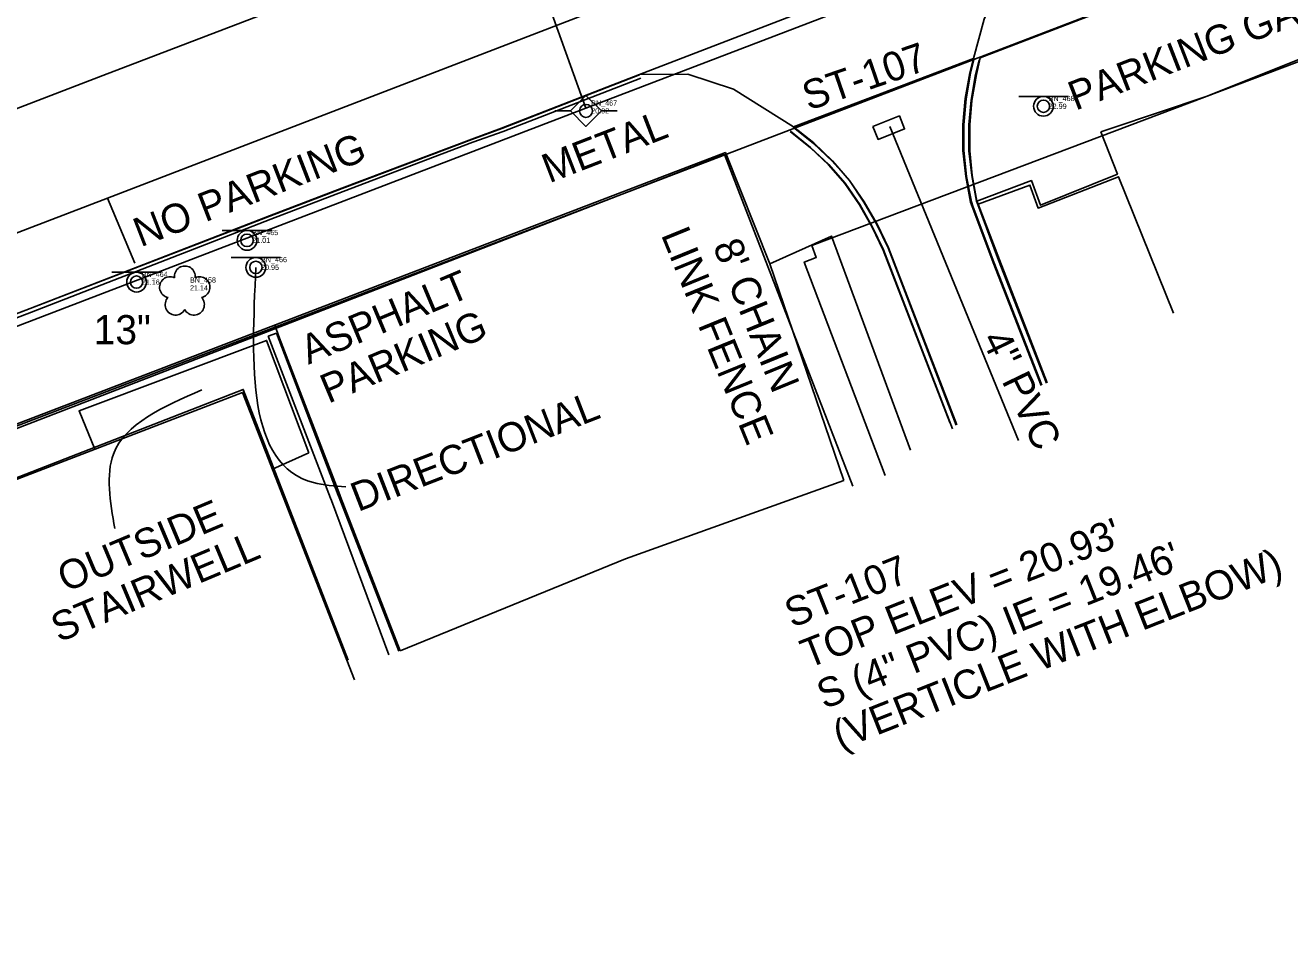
# Model space of a CAD drawing. Extents: x 509744 to 512285, y 1314862 to 1316822.
# Drawn here: x 509949 to 510070.6, y 1315115.3 to 1315204 of the extents above; entities that cross this region are included whole.
import ezdxf

# ---------------------------------------------------------------- set-up
doc = ezdxf.new("R2010")
doc.units = 0
for name, color, linetype in [('Building_ep', 7, 'Continuous'), ('CatchBasin_ep', 7, 'Continuous'), ('CGBack_ep', 7, 'Continuous'), ('CGFace_ep', 7, 'Continuous'), ('ConcSlabs_ep', 7, 'Continuous'), ('Driveway_ep', 7, 'Continuous'), ('ElecAer_ep', 7, 'Continuous'), ('Fence_ep', 7, 'Continuous'), ('LaneLine_ep', 7, 'Continuous'), ('NonPlottingEle_dp', 7, 'Continuous'), ('PavtAsphalt_ep', 7, 'Continuous'), ('PavtBreak_ep', 7, 'Continuous'), ('PavtMisc_ep', 7, 'Continuous'), ('PipeCulvert_ep', 7, 'Continuous'), ('PMRK_ep', 7, 'Continuous'), ('PoleShared_ep', 7, 'Continuous'), ('RWLine_ep', 7, 'Continuous'), ('SidewalkBack_ep', 7, 'Continuous'), ('SignSingle_ep', 7, 'Continuous'), ('Slopes_ep', 7, 'Continuous'), ('TextElevLabel', 7, 'Continuous'), ('TextPtLabel', 7, 'Continuous'), ('TextTopoLabel_ep', 7, 'Continuous'), ('TextUtilLabel_ep', 7, 'Continuous'), ('Tree_ep', 7, 'Continuous')]:
    doc.layers.add(name, color=color, linetype=linetype)

msp = doc.modelspace()

# ---------------------------------------------------------------- linework, layer by layer
at = {"layer": 'Building_ep'}
msp.add_line((509976.25, 1315162.89), (509972.77, 1315161.34), dxfattribs=at)
for points in [[(510031.67, 1315160.73), (510023.9, 1315181.24), (510025.05, 1315181.67), (510024.61, 1315182.82), (510259.1, 1315271.46), (510282.99, 1315280.49), (510283.72, 1315280.77), (510283.22, 1315282.11), (510309.92, 1315292.28), (510311.75, 1315292.98), (510312.2, 1315291.8), (510313.38, 1315292.25), (510318.66, 1315278.4)], [(509955.69, 1315163.24), (509954.18, 1315166.93), (509972.2, 1315173.7), (509976.25, 1315162.89)], [(509838.61, 1315118.22), (509969.9, 1315168.71), (509980.66, 1315141.08)]]:
    msp.add_lwpolyline(points, dxfattribs=at)
at = {"layer": 'CatchBasin_ep'}
msp.add_lwpolyline([(510030.5, 1315194.29), (510033.04, 1315195.29), (510033.54, 1315194.04), (510031, 1315193.04)], close=True, dxfattribs=at)
at = {"layer": 'CGBack_ep'}
for points in [[(510040.72, 1315200.67), (510040.37, 1315199.29), (510039.93, 1315196.81), (510039.73, 1315194.44), (510039.73, 1315191.94), (510040, 1315189.55), (510040.46, 1315187.1), (510040.57, 1315186.79), (510042.57, 1315181.42), (510047.18, 1315169.59)], [(509813.71, 1315124.27), (509825.79, 1315128.91), (509831.2, 1315131.02), (509839.43, 1315134.21), (509846.9, 1315137.07), (509851.56, 1315138.88), (509884.3, 1315151.27), (509916.92, 1315163.93), (509949.61, 1315176.43), (509972.61, 1315185.37), (509979.57, 1315188.02), (509992.04, 1315192.76), (509994.94, 1315193.78), (510005.05, 1315197.7), (510008.18, 1315198.91)], [(510022.56, 1315193.82), (510024.51, 1315192.27), (510026.26, 1315190.62), (510027.83, 1315188.82), (510029.23, 1315186.77), (510030.46, 1315184.6), (510031.52, 1315182.42), (510038.15, 1315165.22)], [(509972.35, 1315174.12), (509978.36, 1315158.53), (509978.43, 1315158.31), (509983.97, 1315143.48)]]:
    msp.add_lwpolyline(points, dxfattribs=at)
at = {"layer": 'CGFace_ep'}
msp.add_line((509972.35, 1315174.12), (509973.15, 1315174.4), dxfattribs=at)
for points in [[(510040.22, 1315200.8), (510039.89, 1315199.41), (510039.45, 1315196.95), (510039.23, 1315194.45), (510039.23, 1315191.96), (510039.5, 1315189.48), (510039.97, 1315187.02), (510040.11, 1315186.6), (510042.13, 1315181.23), (510046.74, 1315169.4)], [(509813.59, 1315124.59), (509825.66, 1315129.25), (509831.06, 1315131.39), (509839.29, 1315134.56), (509846.77, 1315137.4), (509851.43, 1315139.21), (509884.16, 1315151.63), (509916.8, 1315164.26), (509949.48, 1315176.78), (509972.5, 1315185.65), (509979.46, 1315188.3), (509991.93, 1315193.04), (509994.82, 1315194.09), (510004.92, 1315198.02), (510008.05, 1315199.23)], [(510022.82, 1315194.2), (510024.78, 1315192.65), (510026.59, 1315190.94), (510028.23, 1315189.07), (510029.63, 1315187.01), (510030.86, 1315184.85), (510031.95, 1315182.6), (510038.49, 1315165.56)], [(509984.92, 1315143.81), (509979.19, 1315158.6), (509979.09, 1315158.81), (509973.15, 1315174.4)]]:
    msp.add_lwpolyline(points, dxfattribs=at)
at = {"layer": 'ConcSlabs_ep'}
msp.add_lwpolyline([(510040.63, 1315186.81), (510045.59, 1315188.64), (510046.37, 1315186.43), (510054.11, 1315189.45), (510059.39, 1315176.32)], dxfattribs=at)
at = {"layer": 'Driveway_ep'}
msp.add_line((510020.58, 1315181.06), (510027.7, 1315160.24), dxfattribs=at)
for points in [[(510045.95, 1315213.87), (510042.88, 1315208.24), (510041.2, 1315204.61), (510040.15, 1315200.82), (510039.82, 1315199.43), (510039.38, 1315196.98), (510039.15, 1315194.45), (510039.15, 1315191.96), (510039.43, 1315189.47), (510039.89, 1315187.01), (510040.04, 1315186.57), (510042.06, 1315181.2), (510046.67, 1315169.38)], [(510008.04, 1315199.27), (510012.69, 1315199.32), (510017.1, 1315197.85), (510022.85, 1315194.24), (510024.8, 1315192.69), (510026.62, 1315190.97), (510028.26, 1315189.09), (510029.66, 1315187.03), (510030.89, 1315184.87), (510031.99, 1315182.61), (510038.56, 1315165.59)], [(509972.98, 1315175.18), (509973.44, 1315173.91), (509979.23, 1315158.87), (509979.31, 1315158.65), (509985.03, 1315143.85)]]:
    msp.add_lwpolyline(points, dxfattribs=at)
at = {"layer": 'ElecAer_ep'}
msp.add_line((510002.91, 1315196.03), (509981.67, 1315254.87), dxfattribs=at)
msp.add_lwpolyline([(510322.54, 1315318.27), (510002.91, 1315196.03), (509851.1, 1315137.82), (509841.44, 1315118.67)], dxfattribs=at)
at = {"layer": 'Fence_ep'}
msp.add_lwpolyline([(510028.58, 1315159.69), (510016.24, 1315191.57), (509972.9, 1315174.8), (509819.68, 1315115.6)], dxfattribs=at)
at = {"layer": 'LaneLine_ep'}
msp.add_lwpolyline([(510329.98, 1315342.27), (510306.63, 1315333.33), (510283.28, 1315324.38), (510259.94, 1315315.44), (510236.59, 1315306.49), (510213.25, 1315297.55), (510189.9, 1315288.61), (510166.56, 1315279.66), (510143.21, 1315270.72), (510119.87, 1315261.77), (510096.52, 1315252.83), (510073.18, 1315243.89), (510049.83, 1315234.94), (510026.49, 1315226), (510003.14, 1315217.05), (509979.8, 1315208.11), (509956.45, 1315199.17), (509933.11, 1315190.22), (509909.76, 1315181.28), (509886.41, 1315172.33), (509863.07, 1315163.39), (509839.72, 1315154.44), (509808.5, 1315142.48)], dxfattribs=at)
at = {"layer": 'PavtAsphalt_ep'}
msp.add_lwpolyline([(509813.54, 1315124.7), (509825.63, 1315129.33), (509831.05, 1315131.4), (509839.29, 1315134.57), (509846.77, 1315137.41), (509851.43, 1315139.22), (509884.12, 1315151.73), (509916.79, 1315164.27), (509949.48, 1315176.78), (509972.49, 1315185.69), (509979.45, 1315188.33), (509991.92, 1315193.07), (509994.8, 1315194.13), (510004.91, 1315198.06), (510008.04, 1315199.27), (510040.7, 1315211.86), (510048.47, 1315214.83), (510051.93, 1315216.06), (510084.65, 1315228.47), (510117.34, 1315240.98), (510150.02, 1315253.51), (510182.71, 1315266), (510215.38, 1315278.54), (510256.49, 1315294.51)], dxfattribs=at)
at = {"layer": 'PavtBreak_ep'}
msp.add_line((510022.85, 1315194.24), (510040.15, 1315200.82), dxfattribs=at)
msp.add_lwpolyline([(509956.9, 1315187.39), (509980.24, 1315196.35), (510003.58, 1315205.32), (510026.92, 1315214.28), (510050.25, 1315223.25), (510054.84, 1315225.01)], dxfattribs=at)
at = {"layer": 'PavtMisc_ep'}
for points in [[(510244.98, 1315267.81), (510208.36, 1315253.88), (510148.37, 1315230.91), (510099.37, 1315211.92), (510062.55, 1315197.17), (510053.37, 1315194.09)], [(510040.5, 1315187.1), (510045.74, 1315189.07), (510046.62, 1315186.71), (510054.01, 1315189.7), (510052.42, 1315193.76)], [(510052.42, 1315193.76), (510053.37, 1315194.09)], [(509985.03, 1315143.85), (510006.71, 1315152.71), (510027.7, 1315160.24)]]:
    msp.add_lwpolyline(points, dxfattribs=at)
at = {"layer": 'PipeCulvert_ep'}
msp.add_line((510032.12, 1315194.29), (510044.49, 1315164.07), dxfattribs=at)
at = {"layer": 'PMRK_ep'}
for points in [[(509956.9, 1315187.39), (509889.16, 1315161.41)], [(509959.55, 1315181.13), (509956.9, 1315187.39)]]:
    msp.add_lwpolyline(points, dxfattribs=at)
at = {"layer": 'PoleShared_ep'}
for p, q in [((509999.92, 1315195.78), (510001.42, 1315195.78)), ((510005.9, 1315195.78), (510004.4, 1315195.78))]:
    msp.add_line(p, q, dxfattribs=at)
msp.add_lwpolyline([(510001.42, 1315195.78), (510002.91, 1315197.27), (510004.4, 1315195.78), (510002.91, 1315194.29), (510001.42, 1315195.78)], dxfattribs=at)
msp.add_circle((510002.91, 1315195.78), 0.625, dxfattribs=at)
at = {"layer": 'RWLine_ep'}
msp.add_line((509817.13, 1315115.31), (510540.74, 1315392.41), dxfattribs=at)
at = {"layer": 'SidewalkBack_ep'}
for points in [[(510047.26, 1315169.62), (510042.65, 1315181.45), (510040.63, 1315186.81), (510040.5, 1315187.1), (510040.03, 1315189.56), (510039.81, 1315191.94), (510039.81, 1315194.44), (510040.01, 1315196.79), (510040.45, 1315199.27), (510040.81, 1315200.88), (510064.15, 1315209.84), (510087.49, 1315218.79), (510110.83, 1315227.75), (510134.17, 1315236.71), (510157.51, 1315245.66), (510180.85, 1315254.62), (510204.2, 1315263.57), (510227.54, 1315272.53), (510250.88, 1315281.48), (510274.22, 1315290.44), (510277.93, 1315291.86)], [(510022.54, 1315193.8), (510024.48, 1315192.23), (510026.22, 1315190.59), (510027.78, 1315188.8), (510029.19, 1315186.74), (510030.42, 1315184.58), (510031.47, 1315182.4), (510037.89, 1315165.82)], [(509817.13, 1315115.51), (509829.53, 1315120.26), (509852.88, 1315129.2), (509876.23, 1315138.14), (509899.57, 1315147.08), (509922.92, 1315156.02), (509946.27, 1315164.96), (509969.62, 1315173.89), (509992.96, 1315182.83), (510016.31, 1315191.77), (510020.58, 1315181.06), (510026.51, 1315183.74), (510034.11, 1315163.14)]]:
    msp.add_lwpolyline(points, dxfattribs=at)
at = {"layer": 'SignSingle_ep'}
for p, q in [((510044.51, 1315197.17), (510049.26, 1315197.17)), ((509967.94, 1315184.28), (509972.69, 1315184.28)), ((509968.8, 1315181.68), (509973.55, 1315181.68)), ((509957.32, 1315180.26), (509962.07, 1315180.26))]:
    msp.add_line(p, q, dxfattribs=at)
for centre, radius in [((510046.89, 1315196.22), 0.95), ((510046.89, 1315196.22), 0.594), ((509970.32, 1315183.33), 0.95), ((509970.32, 1315183.33), 0.594), ((509971.17, 1315180.73), 0.95), ((509971.17, 1315180.73), 0.594), ((509959.7, 1315179.31), 0.95), ((509959.7, 1315179.31), 0.594)]:
    msp.add_circle(centre, radius, dxfattribs=at)
at = {"layer": 'Slopes_ep'}
msp.add_lwpolyline([(509980.03, 1315142.95), (509969.95, 1315168.99), (509924.51, 1315151.28), (509884.5, 1315135.91), (509856.15, 1315125.1), (509838.49, 1315118.26)], dxfattribs=at)
at = {"layer": 'TextTopoLabel_ep'}
for points in [[(509979.82, 1315159.62), (509976.71, 1315160.03), (509971.17, 1315180.73)], [(509965.96, 1315168.95), (509957.48, 1315162.78), (509957.61, 1315155.63)]]:
    msp.add_spline(points, degree=3, dxfattribs=at)
at = {"layer": 'Tree_ep'}
for centre, start, end in [((509964.34, 1315179.86), 352.1546, 187.8454), ((509962.91, 1315178.82), 64.1546, 259.8454), ((509965.76, 1315178.82), 280.1546, 115.8454), ((509963.45, 1315177.14), 136.1546, 331.8454), ((509965.22, 1315177.14), 208.1546, 43.8454)]:
    msp.add_arc(centre, 1, start, end, dxfattribs=at)

# ---------------------------------------------------------------- texts
at = {"layer": 'NonPlottingEle_dp'}
for s, rotation, p in [('ST-107', 18.9888, (510024.31, 1315195.78)), ('4" PVC', 295.8171, (510040.9, 1315173.84)), ("TOP ELEV = 20.93'", 21.5246, (510024.26, 1315142.13)), ('S (4" PVC) IE = 19.46\'', 21.5246, (510025.81, 1315138.22)), ('ST-107', 21.5246, (510022.72, 1315146.04)), ('(VERTICLE WITH ELBOW)', 21.5246, (510027.35, 1315134.32))]:
    msp.add_text(s, height=2.8, rotation=rotation, dxfattribs=at).set_placement(p)
at = {"layer": 'TextElevLabel'}
for s, p in [('20.92', (510003.41, 1315195.53)), ('22.99', (510047.39, 1315195.97)), ('21.01', (509970.82, 1315183.08)), ('20.95', (509971.67, 1315180.48)), ('21.16', (509960.2, 1315179.06)), ('21.14', (509964.84, 1315178.51))]:
    msp.add_text(s, height=0.5, dxfattribs=at).set_placement(p)
at = {"layer": 'TextPtLabel'}
for s, p in [('BN_467', (510003.41, 1315196.28)), ('BN_468', (510047.39, 1315196.72)), ('BN_465', (509970.82, 1315183.83)), ('BN_466', (509971.67, 1315181.23)), ('BN_464', (509960.2, 1315179.81)), ('BN_458', (509964.84, 1315179.26))]:
    msp.add_text(s, height=0.5, dxfattribs=at).set_placement(p)
at = {"layer": 'TextTopoLabel_ep'}
for s, rotation, p in [('PARKING GARAGE FEES', 21.2365, (510049.97, 1315195.78)), ('NO PARKING', 21.1862, (509960.09, 1315182.65)), ('LINK FENCE', 292.2353, (510010.09, 1315183.88)), ("8' CHAIN", 292.2353, (510015.07, 1315182.79)), ('ASPHALT', 22.7781, (509976.22, 1315171.36)), ('PARKING', 22.7781, (509978.13, 1315167.61)), ('DIRECTIONAL', 21.1862, (509980.99, 1315157.2)), ('OUTSIDE', 22.7781, (509952.87, 1315149.46)), ('STAIRWELL', 22.7781, (509952.24, 1315144.64))]:
    msp.add_text(s, height=2.8, rotation=rotation, dxfattribs=at).set_placement(p)
msp.add_text('13"', height=2.8, dxfattribs=at).set_placement((509955.58, 1315173.34))
at = {"layer": 'TextUtilLabel_ep'}
msp.add_text('METAL', height=2.8, rotation=21.1824, dxfattribs=at).set_placement((509999.37, 1315188.8))

doc.saveas('drawing.dxf')
